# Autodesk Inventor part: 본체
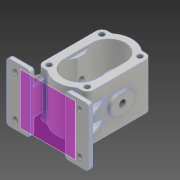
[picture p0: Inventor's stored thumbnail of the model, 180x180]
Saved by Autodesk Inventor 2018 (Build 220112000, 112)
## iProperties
Created: 2023-06
Part Number: 본체
Material: 알루미늄 6061
Document SubType Name: Modeling
Designer: 강의실01
Density: 2.7 g/cm^3
Appearance: 알루미늄 - 평지
Mass: 1266.86 g
Surface Area: 986.48 cm^2
Volume: 469.209 cm^3
Author: 강의실01
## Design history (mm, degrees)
sketch "스케치1"
  geometry: L1 (-42.5, -45)-(-42.5, 45); L2 (42.5, 45)-(42.5, -45); L3 (42.5, -55)-(-42.5, 55); L4 (-42.5, -55)-(42.5, 55); L5 (-24, -24)-(24, 24); L6 (24, -24)-(-24, 24); L7 (-32.5, 55)-(-25.278, 55); L8 (25.278, 55)-(32.5, 55); L9 (32.5, -55)-(25.278, -55); L10 (-25.278, -55)-(-32.5, -55); L11 (22.5, 6.507)-(22.5, -6.507); L12 (-22.5, -6.507)-(-22.5, 6.507); L13 (-22.5, 22.5)-(22.5, -22.5); L14 (22.5, 22.5)-(-22.5, -22.5); A1 r 10 centre (-32.5, 45) between (-32.5, 55) and (-42.5, 45); A2 r 10 centre (32.5, 45) between (42.5, 45) and (32.5, 55); A3 r 10 centre (32.5, -45) between (32.5, -55) and (42.5, -45); A4 r 10 centre (-32.5, -45) between (-42.5, -45) and (-32.5, -55); A5 r 40 centre (0, -24) between (-25.278, -55) and (25.278, -55); A6 r 40 centre (0, 24) between (25.278, 55) and (-25.278, 55); A7 r 28.5 centre (0, 24) between (22.5, 6.507) and (-22.5, 6.507); A8 r 28.5 centre (0, -24) between (-22.5, -6.507) and (22.5, -6.507); 1 further point
  constraints: 28 end point, 16 point on circle, 14 tangent, 8 centre point, 6 midpoint, 6 parallel, 5 equal radius, 4 perpendicular, 4 point on line, 2 coincident, 2 collinear, 2 horizontal
  dimensions: "d0" = 85 distance of L3.end L4.end; "d1" = 110 distance of L4.start L3.end; "d2" = 10 radius of A1 (derived); "d3" = 48 distance of L6.end L5.end; "d4" = 48 distance of L5.end L6.start; "d9" = 45 distance of L13.end L14.end; "d10" = 45 distance of L14.start L13.end; "d11" = 40 radius of A6; "d12" = 28.5 radius of A7; "d13" = 45 deg angle of L14 L2; "d14" = 37.6942 deg angle of L4 L2; "d15" = 37.6942 deg angle of L3 L2; "d16" = 110 distance between parallel lines of L10 L8; "d17" = 55 distance from line of point (0, 0) L8; "d18" = 17.22155 distance from line of L8.start L2; "d19" = 17.22155 distance from line of L9.end L2; "d20" = 18.5 distance from line of L5.end L2; "d21" = 20 distance from line of L14.start L2; "d22" = 48.49286 distance from line of L11.start L8; "d23" = 61.50714 distance from line of L11.end L8; "d24" = 65 distance from line of L13.start L2; "d25" = 66.5 distance from line of L5.start L2
extrude "돌출1" new body sketch "스케치1" stored distance "d26" = 79; taper "d27" = 0 deg
sketch "스케치2"
  geometry: L1 (28.5, 24)-(28.5, -24); L2 (-28.5, -24)-(-28.5, 24); L3 (-28.5, 24)-(28.5, 24); L4 (-28.5, -24)-(28.5, -24); A1 r 28.5 centre (0, 24) between (22.5, 6.507) and (-22.5, 6.507) reference; A2 r 28.5 centre (0, -24) between (-22.5, -6.507) and (22.5, -6.507) reference; 1 further point
  constraints: 8 end point, 3 point on circle, 2 vertical, 1 horizontal, 1 perpendicular, 1 tangent
extrude "돌출2" cut sketch "스케치2" distance "d28" = 4.5; taper "d29" = 0 deg
sketch "스케치3"
  geometry: A1 r 10 centre (-32.5, 45) between (-32.5, 55) and (-42.5, 45) reference; A2 r 10 centre (32.5, 45) between (42.5, 45) and (32.5, 55) reference; A3 r 10 centre (32.5, -45) between (32.5, -55) and (42.5, -45) reference; A4 r 10 centre (-32.5, -45) between (-42.5, -45) and (-32.5, -55) reference; 5 further points
  constraints: 4 coincident
hole "구멍1" sketch "스케치3" at (-32.5, 45), (32.5, 45), (32.5, -45), (-32.5, -45) diameter "d30" = 9; stored, may be unused: countersink angle "d34" = 90 deg, drill point angle "d36" = 0 deg; dims "d31" = 6, "d32" = 4, "d33" = 2, "d35" = 79
node "작업 평면1"
sketch "스케치4"
  geometry: L1 (70, -45)-(70, 45); L2 (-70, 45)-(-70, -45); L3 (-70, -50)-(70, 50); L4 (70, -50)-(-70, 50); L5 (-65, -50)-(-35, -50); L6 (-30, -45)-(-30, 45); L7 (-35, 50)-(-65, 50); L8 (-70, 45)-(-70, -45); L9 (65, -50)-(35, -50); L10 (30, -45)-(30, 45); L11 (35, 50)-(65, 50); L12 (70, 45)-(70, -45); L13 (-65, -50)-(-35, -50); L14 (35, -50)-(65, -50); L15 (65, 50)-(35, 50); L16 (-35, 50)-(-65, 50); A1 r 5 centre (65, -45) between (65, -50) and (70, -45); A2 r 5 centre (35, -45) between (30, -45) and (35, -50); A3 r 5 centre (-35, -45) between (-35, -50) and (-30, -45); A4 r 5 centre (-65, -45) between (-70, -45) and (-65, -50); A5 r 5 centre (-65, 45) between (-65, 50) and (-70, 45); A6 r 5 centre (-35, 45) between (-30, 45) and (-35, 50); A7 r 5 centre (35, 45) between (35, 50) and (30, 45); A8 r 5 centre (65, 45) between (70, 45) and (65, 50); 1 further point
  constraints: 32 end point, 17 tangent, 16 point on circle, 9 parallel, 8 centre point, 7 equal radius, 6 point on line, 4 horizontal, 4 perpendicular, 2 midpoint
  dimensions: "d38" = 140 distance of L4.end L3.end; "d39" = 100 distance of L3.end L4.start; "d42" = 54.4623 deg angle of L1 L4; "d43" = 54.4623 deg angle of L3 L12; "d44" = 5 radius of A1; "d45" = 40 distance between parallel lines of L12 L10; "d46" = 40 distance between parallel lines of L2 L6; "d47" = 100 distance between parallel lines of L11 L14
extrude "돌출3" join sketch "스케치4" distance "d48" = 9; taper "d49" = 0 deg
sketch "스케치5" dims "d63" = 10
  geometry: L1 (-30, -45)-(-30, 45) reference; L2 (-30, 0)-(-30, 21); L3 (-30, 0)-(-30, -21); L4 (-34, -25)-(-34, 25); L5 (-30, -21)-(-30, 21); L6 (-38, 21)-(-38, -21); L7 (-34, 0)-(34, 0); L8 (30, 21)-(30, -21); L9 (38, 0)-(38, 21); L10 (38, 0)-(38, -21); L11 (-38, 21)-(-38, 25); L12 (-38, 25)-(-30, 25); L13 (-30, 25)-(-30, 21); L14 (-38, -21)-(-38, -25); L15 (-38, -25)-(-30, -25); L16 (-30, -25)-(-30, -21); L17 (30, -21)-(30, -25); L18 (30, 45)-(30, -45) reference; L19 (30, -25)-(38, -25); L20 (38, -25)-(38, -21); L21 (38, 21)-(38, 25); L22 (38, 25)-(30, 25); L23 (30, 25)-(30, 21); L24 (-38, 25)-(-38, -25); L25 (-30, 25)-(-30, -25); L26 (30, 25)-(30, -25); L27 (38, -25)-(38, 25); A1 r 4 centre (-34, -21) between (-38, -21) and (-30, -21); A2 r 4 centre (-34, 21) between (-30, 21) and (-38, 21); A3 r 4 centre (34, 21) between (38, 21) and (30, 21); A4 r 4 centre (34, -21) between (30, -21) and (38, -21); 1 further point
  constraints: 52 end point, 10 point on circle, 9 tangent, 7 point on line, 4 centre point, 4 perpendicular, 2 collinear, 2 horizontal, 2 midpoint, 2 vertical, 1 parallel, 12 other
  dimensions: "d55" = 50 distance of L4.start L4.end; "d56" = 24 distance of L1.end L2.end; "d57" = 68 distance of L7.start L7.end; "d60" = 68 distance of A2.centre A3.centre; "d85" = 4 distance of L6.start L11.end; "d86" = 8 distance of L11.end L12.end (derived); "d87" = 4 distance of L12.end L2.end (derived); "d88" = 4 distance of L6.end L14.end; "d89" = 8 distance of L14.end L15.end; "d90" = 4 distance of L8.end L17.end; "d91" = 8 distance of L17.end L19.end; "d92" = 4 distance of L9.end L21.end; "d93" = 8 distance of L21.end L22.end (derived)
extrude "돌출4" join sketch "스케치5" stored distance "d65" = 9; taper "d66" = 0 deg
node "작업 평면2"
sketch "스케치7"
  geometry: L1 (-70, -71)-(-62, -71); L2 (-35, -71)-(-65, -71) reference; L3 (-62, -71)-(-42.5, -25.061); L4 (-42.5, -45)-(-42.5, 45) reference; 1 further point
  constraints: 4 end point, 2 point on line
  dimensions: "d68" = 8 distance of L1.start L1.end; "d69" = 113 deg angle of L3 L1
feature "리브1" sketch "스케치7" dims "d70" = 1, "d71" = 7, "d72" = 0, "d73" = 0, "d74" = 1, "d75" = 1
node "작업 평면3"
sketch "스케치8"
  geometry: L1 (-70, -80)-(-70, -71) reference; L2 (-70, -71)-(-62, -71); L3 (-35, -71)-(-65, -71) reference; L4 (-62, -71)-(-42.5, -25.061); L5 (-42.5, -45)-(-42.5, 45) reference; 1 further point
  constraints: 4 end point, 2 point on line
  dimensions: "d77" = 8 distance of L1.end L2.end; "d78" = 113 deg angle of L4 L2
feature "리브2" sketch "스케치8" dims "d79" = 1, "d80" = 7, "d81" = 0, "d82" = 0, "d83" = 1, "d84" = 1
extrude "돌출5" join sketch "스케치5" stored distance "d94" = 9; taper "d95" = 0 deg
sketch "스케치9"
  geometry: L1 (-24.5, 40)-(-24.5, 50); L2 (-54.5, 50)-(-54.5, 40); L3 (-54.5, 40)-(-24.5, 50); L4 (-24.5, 40)-(-54.5, 50); A1 r 15 centre (-39.5, 50) between (-24.5, 50) and (-54.5, 50); A2 r 15 centre (-39.5, 40) between (-54.5, 40) and (-24.5, 40); 1 further point
  constraints: 8 end point, 4 point on circle, 4 tangent, 2 centre point, 2 midpoint, 1 parallel
  dimensions: "d96" = 30 distance of L2.start L1.end; "d97" = 10 distance of L1.end L1.start
extrude "돌출6" join sketch "스케치9" distance "d100" = 5; taper "d101" = 0 deg
sketch "스케치10"
  geometry: L1 (-54.5, 50)-(-54.5, 40) reference; L2 (-24.5, 40)-(-24.5, 50) reference; A1 r 15 centre (-39.5, 40) between (-54.5, 40) and (-24.5, 40) reference; A2 r 15 centre (-39.5, 50) between (-24.5, 50) and (-54.5, 50) reference; 2 further points
  constraints: 1 coincident
hole "구멍2" sketch "스케치10" at (-39.5, 45) diameter "d102" = 10.5; stored, may be unused: countersink angle "d108" = 90 deg, drill point angle "d110" = 0 deg; dims "d103" = 11, "d104" = 0.62479, "d105" = 10.589, "d106" = 4, "d107" = 2, "d109" = 25
sketch "스케치11"
  geometry: L1 (55, 35)-(-55, 35); L2 (-55, 35)-(-55, -35); L3 (-55, -35)-(55, -35); L4 (55, -35)-(55, 35); L5 (55, 35)-(-55, -35); L6 (-55, 35)-(55, -35); C1 r 9 at (55, -35); C2 r 9 at (-55, -35); C3 r 9 at (-55, 35); C4 r 9 at (55, 35); 1 further point
  constraints: 12 end point, 4 centre point, 4 coincident, 2 midpoint, 2 parallel, 1 horizontal, 1 perpendicular
  dimensions: "d111" = 110 distance of L3.end L2.end; "d112" = 70 distance of L2.end L1.end; "d113" = 18 diameter of C1; "d114" = 18 diameter of C2; "d115" = 18 diameter of C3; "d116" = 18 diameter of C4
extrude "돌출7" join sketch "스케치11" distance "d117" = 3; taper "d118" = 0 deg
sketch "스케치12"
  geometry: C1 r 9 at (-110, 0) reference; C2 r 9 at (-110, 70) reference; C3 r 9 at (0, 70) reference; C4 r 9 at (0, 0) reference; 5 further points
  constraints: 4 coincident
hole "구멍3" sketch "스케치12" at (-110, 0), (-110, 70), (0, 70), (0, 0) diameter "d119" = 9; stored, may be unused: countersink angle "d123" = 90 deg, drill point angle "d125" = 0 deg; dims "d120" = 11, "d121" = 4, "d122" = 2, "d124" = 25
node "작업 평면4"
sketch "스케치13"
  geometry: 2 further points
  constraints: 1 vertical alignment, 1 other
  dimensions: "d127" = 20 distance of point (0, 0) point (0, -20)
feature "엠보싱1" sketch "스케치13" dims "d0" = 85, "d1" = 110, "d2" = 10 (derived), "d3" = 48, "d4" = 48, "d9" = 45, "d10" = 45, "d11" = 40, "d12" = 28.5, "d13" = 45 deg, "d14" = 6.57889, "d15" = 6.57889, "d16" = 110, "d17" = 55, "d18" = 17.22155, "d19" = 17.22155, "d20" = 18.5, "d21" = 20, "d22" = 48.49286, "d23" = 61.50714, "d24" = 65, "d25" = 66.5, "d128" = 0.5, "d129" = 0
fillet "모깎기1" dims "d130" = 3
fillet "모깎기2" dims "d131" = 3
fillet "모깎기3" dims "d132" = 3
fillet "모깎기4" dims "d133" = 3
node "솔리드1"
mirror "미러1"
mirror "미러2"
mirror "미러3"
mirror "미러4"
node "투영된 루프1"
other parameters: "d7" = 57, "d8" = 57, "d67" = 11, "d76" = -11, "d126" = 144
